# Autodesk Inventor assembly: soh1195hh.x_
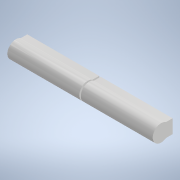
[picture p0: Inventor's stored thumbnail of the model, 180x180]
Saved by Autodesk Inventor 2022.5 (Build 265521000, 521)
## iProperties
Created: 2023-06
Part Number: soh1195hh.x_
Document SubType Name: Assembly
Designer: ImaoCorp
Sending System: SOLIDWORKS 2021-2021301
MC: AMD64
MC_MODEL: Intel64 Family 6 Model 60 Stepping 3, GenuineIntel
OS: Windows_NT
FRU: Parasolid Version 32.1, build 255,  1- 1-2021
FORMAT: text
GUISE: transmit
KEY: soh1195hh
FILE: soh1195hh.x_t
DATE: Thu Jun 15 16:15:40 2023
Author: ImaoCorp
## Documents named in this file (3)
- X:\14_SW2022-Inv2022\00_全2023-1023新製品(TCC)まで\s\soh1195hh\SOH1195HH.iam
- X:\14_SW2022-Inv2022\00_全2023-1023新製品(TCC)まで\s\soh1195hh\soh1195hh_01.ipt
- X:\14_SW2022-Inv2022\00_全2023-1023新製品(TCC)まで\s\soh1195hh\soh1195hh_02.ipt
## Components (2 placed, 2 different names)
1. soh1195hh_01
2. soh1195hh_02
